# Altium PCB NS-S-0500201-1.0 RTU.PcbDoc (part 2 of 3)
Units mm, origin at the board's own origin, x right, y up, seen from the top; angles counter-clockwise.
Board outline 170 x 90 mm, 6 copper layers (TOP, L2_GND, L3_SIG, L4_VCC, L5_GND, BOT), stack 1.4 mm thick; 260 components, 230 nets, 1133 pads, 705 vias.
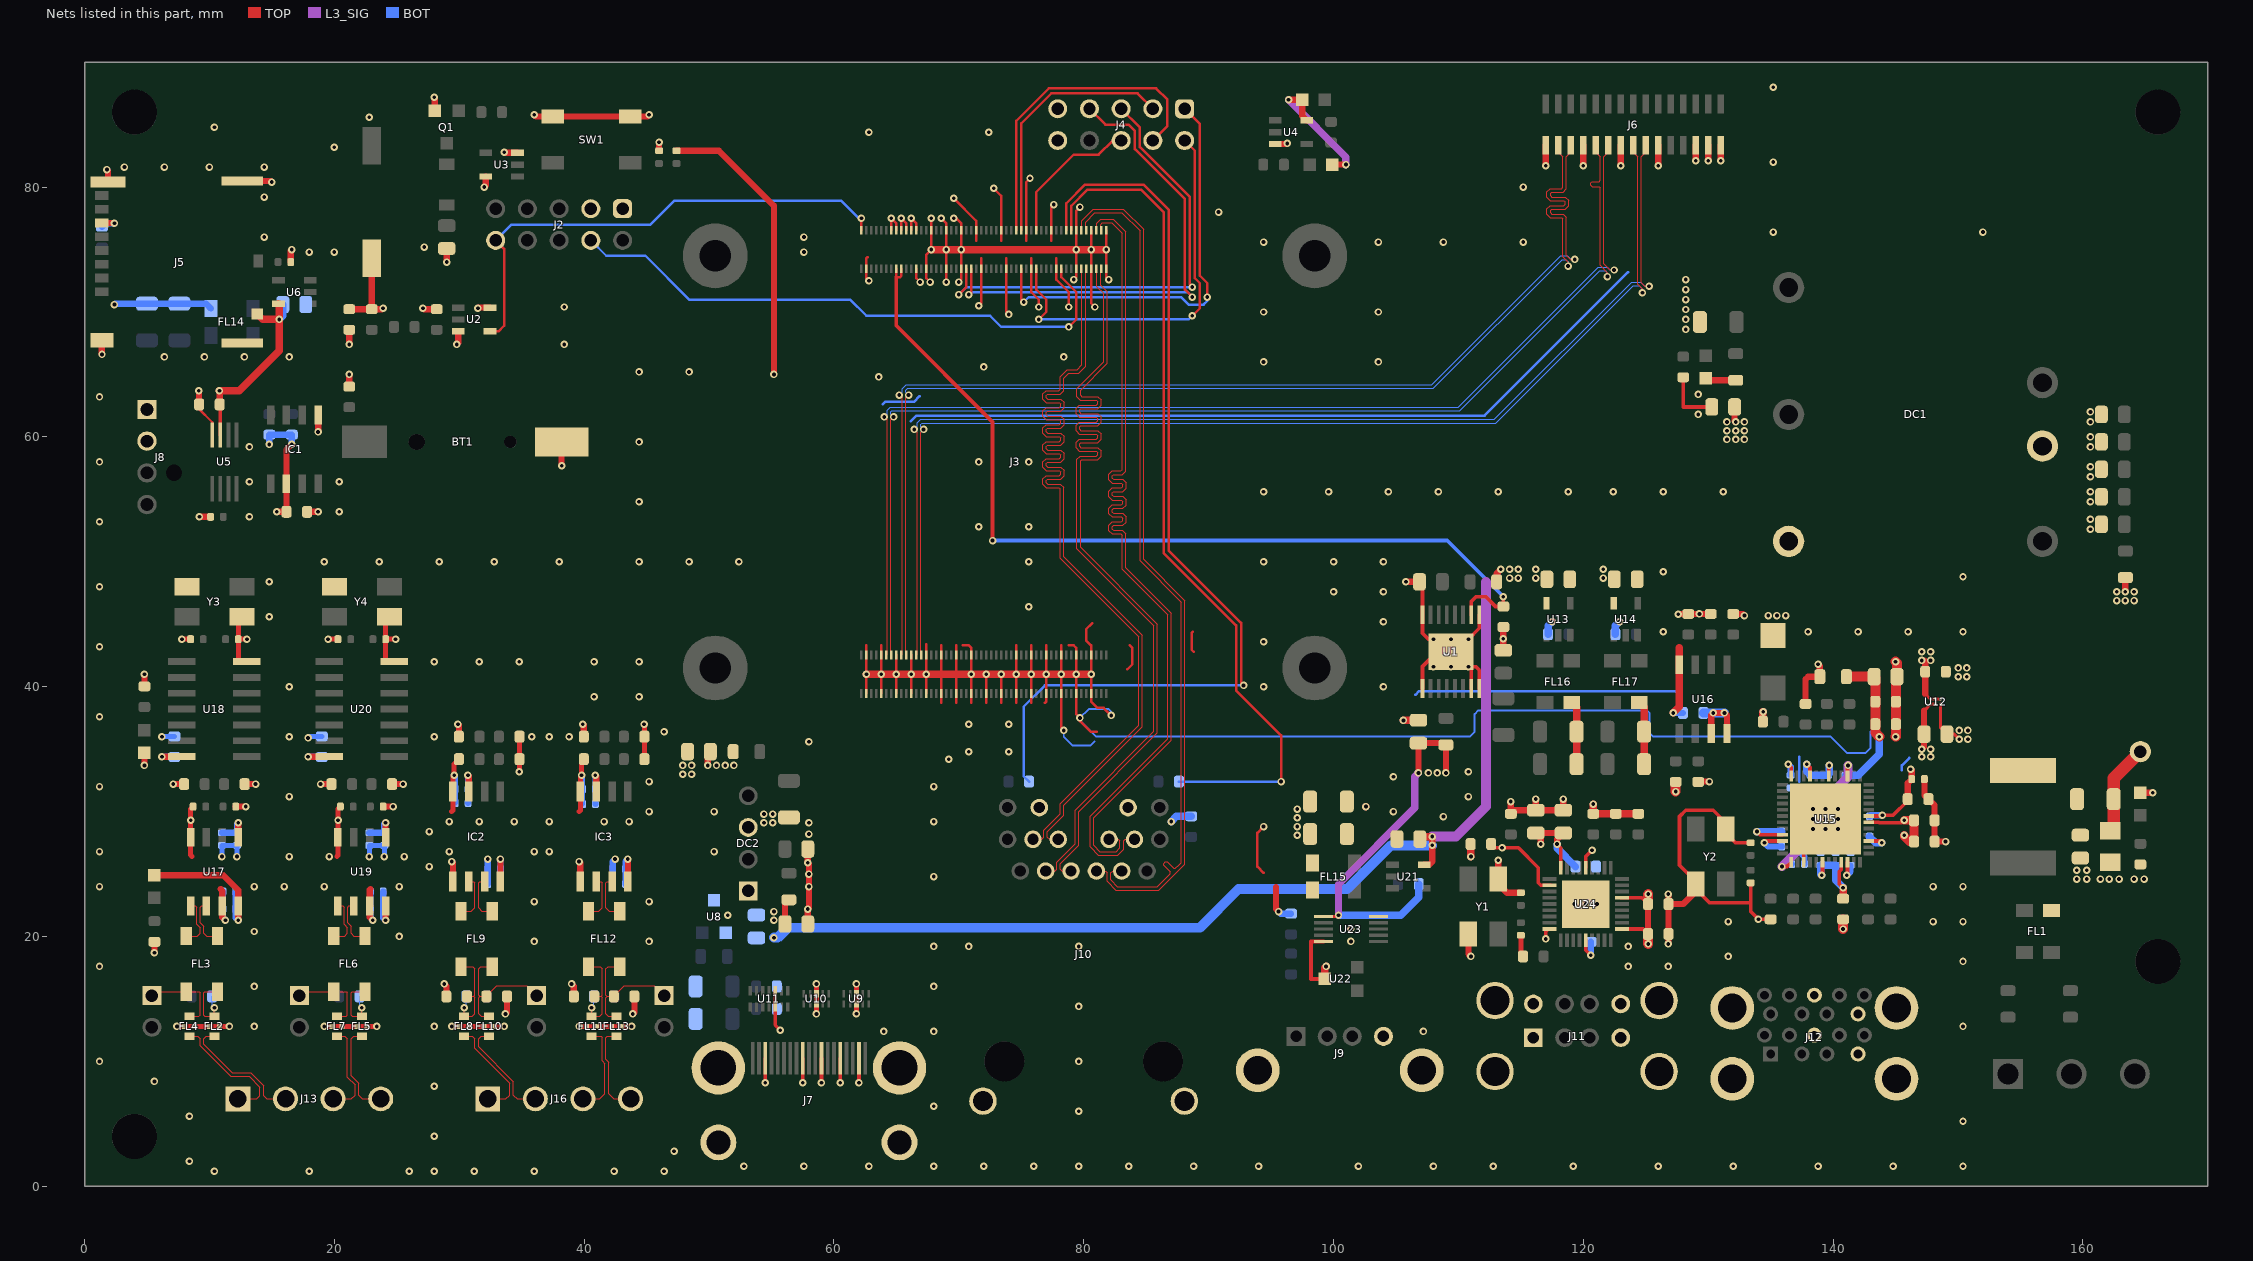
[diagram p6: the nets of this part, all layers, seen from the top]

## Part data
3V3 5V 5V_ISO 24V CPU_RUN PWR_ON: "Standard LEDs - SMD SMD 1608(mm) GREEN", Package=1608, PartNo.="LED GREEN[1608]"
BT1: "Battery Holder (CR1220 Need)", Package="Battery holder 1220 SMD"
C1 C2 C3 C4 C5: "MLCC - SMD/SMT 35V X5R +/-20% 2012(mm)", Package=2012
C8 C11: "Multilayer Ceramic Capacitors MLCC - SMD/SMT 2Kvolts 1000pF 10% X7R", Package=3216
C9 C10 C12 C13 C16 C17 C18 C29 C30 C35 C36 C37 C64 C67 C68 C77: "MLCC - SMD/SMT 50V X5R +/-10% 2012(mm)", Package=2012
C14 C15 C26: library part "C [3216]_10V", "MLCC - SMD/SMT 10V X5R +/-10% 3216(mm)", Package=3216
C19 C45 C46 C47 C48 C49 C53 C54 C55 C56 C57 C58 C61 C62 C65 C66 C85 C86 C88 C89 C90 C91 C93 C94 C95 C96 C98 C99 C100 C101 C102 C103 C104 C105 C106 C107 C108 C109 C112 C113 C114 C115: "MLCC - SMD/SMT 50V X5R +/-10% 1005(mm)", Package=1005
C20 C21 C22 C23 C24 C25 C33 C34 C38 C39 C40 C41 C42 C43 C44 C50 C51 C52 C59 C60 C63 C78 C79 C80 C81 C82 C83 C84 C87 C92 C97 C110 C111 C116 C117: "MLCC - SMD/SMT 50V X5R +/-10% 1608(mm)", Package=1608
C27 C28 C31 C32 C69 C70 C71 C72 C73 C74: "MLCC - SMD/SMT 50V X5R +/-10% 3216(mm)", Package=3216
D1: "Diodes - General Purpose, Power, Switching SURFACE MOUNT FAST SWITCHING DIODE", Manufacturer_Name="Diodes Inc.", Mouser Part Number=621-1N4148W-F, Package=SOD-123
D2: "Schottky Diodes & Rectifiers 1.0 Amp 40 Volt", Package="SMA (DO-214AC)"
DC1: "20W isolated DC-DC converter DIP package, Ultra-wide input and regulated single output", Package="6-DIP Module"
DC2: "Isolated Module DC DC Converter 1 Output 5V 600mA 4.5V - 5.5V Input", Package="4-SIP Module", Supplier Part Number 1=945-2626-ND
FGND: "TEST POINT 1PI", Package="1mm lead", PartNo.=ST-1-1
FL1 FL14 FL15 FL16 FL17: "CMC,filter , 3.2x2.5x2.2mm,500ohm+/-25%,2A,shd", Package=3225
FL2 FL4 FL5 FL7 FL8 FL10 FL11 FL13: library part YFF18SC1H222M, "Eia Case Size: 0603, Voltage: 50, Cap Value: 472, Tol: +/-20%, Thickness: 0.60 ± 0.10", Arrow Part Number=YFF18SC1H222MT0H0N, Capacitance=4.7nF, Case Code (Imperial)=0603, Case Code (Metric)=1608, Current=1A, DC Resistance (DCR)=300mR, Manufacturer=TDK, Max Operating Temperature=125°C, Min Operating Temperature=-55°C, Supplier Part Number 1=445-16139-1-ND, Tolerance=20%, Voltage Rating=50V
FL3 FL6 FL9 FL12: "CMC 11UH 360MA 2LN SMD AEC-Q200", Case Code (Imperial)=1812, Case Code (Metric)=4532, Current=360mA, DC Resistance (DCR)=500mR, Inductance=11uH, Manufacturer=Murata, Manufacturer_Name="Murata Electronics", Max Operating Temperature=125°C, Min Operating Temperature=-40°C, Mouser Part Number=81-DLW43SH110XK2L, Package Quantity=1, Test Frequency=100MHz, Tolerance=50%
FUSE1: "Resettable Fuses - PPTC PTC RESETTABLE 1.85A 33V SMD 2920", Package=2920(7351), Supplier Part Number 1=652-MF-LSMF185/33X-2
H1 H2 H3 H4: "HOLE", Package=Hole
IC1: "DS3232M Series 4.5 V ±5 ppm Surface Mount I2C Real-Time Clock - SOIC-8", Case/Package=SOIC, Manufacturer=Maxim, Manufacturer_Name="Maxim Integrated", Max Operating Temperature=85°C, Max Supply Voltage=4.5V, Min Operating Temperature=-40°C, Min Supply Voltage=2.3V, Mouser Part Number=700-DS3232MZ+, Package=SOIC-8, Package Quantity=100
IC2 IC3: "RS422/RS485 Transceiver, -40 to 85DEG C Rohs Compliant: Yes", Manufacturer=Maxim, Package=SOIC-Wide-8, PartNo.=MAX22026AWA+, Supplier Part Number 1=700-MAX22026AWA+
J1: "Connector"
J2 J4: "Headers & Wire Housings 10P M PIN HEADER DR STRAIGHT TYPE GOLD", Package="2.54mm Dual 26pin Header straight type", Supplier Part Number 1=798-A110PA254DSA71
J3: "Board to Board & Mezzanine Connectors 100P 2R 3MM RECPT SMT VERT 0.4MM PITCH", Package="0.4mm 100p", Supplier Part Number 1=798-DF40HC30100DS451
J5: "Memory Card Connectors MICRO SD PUSH/PUSH NORMAL 1.28MM 8C", Package="Micro SD"
J6: "Raspberry Pi Accessories Replacement CSI/DSI Connector for Raspberry Pi - Repair Part", Package="FPC 1mm 15pin", Supplier Part Number 1=485-4728
J7: library part 2086581051, "HDMI 2.1 Receptacle Connector 19 Position Surface Mount, Right Angle; Through Hole", Package=HDMI, Supplier Part Number 1=538-208658-1051
J8: "KK 254 Vertical Header, with Friction Lock, 4 Circuits, PC Tail Length 3.50mm, Bag", Current Rating=4A, Housing Color=Beige, Max Operating Temperature=75°C, Min Operating Temperature=0°C, Package Quantity=12000, Supplier Part Number=538-47053-1000, Voltage Rating=250V
J9: "USB 2.0 A/F Connector, Right angle", Package="USB2.0 A/F"
J10: "Gigabit Ethernet Connectors 8/8 RA Magnetic Jack Grn/Orange/Grn LED", Package=RJ45, Supplier Part Number 1=538-85793-1003
J11: "USB 2.0 A/F 2 stack Connector, Right angle", Package="USB2.0 A/F"
J12: "USB 3.0 A/F 2 stack Connector, Right angle", Package="USB3.0 A/F"
J13 J16: "Through Hole 4p right angle DIP (MRT8P3.81-04P need)", Package="Through Hole 4p right angle DIP"
J14 J15 J17 J18: "Headers & Wire Housings 2P M PIN HEADER SR STRAIGHT TYPE GOLD", Package="2P Dual Straight DIP Through Hole", Supplier Part Number 1=H123034-ND
L1 L2 L5 L6 L7 L8 L9 L10 L11 L12: "Ferrite Beads Multi-Layer 120Ohm 25% 100MHz 3A 30mOhm DCR 0805 Paper T/R", Case Code (Imperial)=0805, Case Code (Metric)=2012, Current Rating=3A, DC Resistance (DCR)=30mR, Manufacturer=Murata, Max Operating Temperature=125°C, Min Operating Temperature=-55°C, Package="SMD 2012", Package Quantity=1, Supplier Part Number 1=81-BLM21PG121SN1D, Test Frequency=100MHz, Tolerance=25%
LS1: "9 mm, 5 Vdc, 90 dB, SMD Passive, Magnetic Audio Indicator Buzzer"
Q1: "MOSFET (N-Channel)", Manufacturer_Name="ON Semiconductor", Mouser Part Number=512-BSS138
R1 R2 R3 R4 R8 R9 R12 R13 R14 R15 R21 R22 R28 R29 R30 R31 R32 R33 R34 R35 R36 R37 R38 R39 R40 R41 R42 R43 R44 R45 R46 R47 R48 R49 R50 R51 R52 R53 R54 R55 R56 R57 R58 R59 R60: "SMD  Chip Resistor +/-5% 1608(mm)", Package=1608/J
R5: "SMD  Chip Resistor +/-5% 2012(mm)", Package=2012/J
R6 R11: "SMD  Chip Resistor +/-1% 1608(mm)", Package=1608
R7: "SMD  Chip Resistor +/-1% 2012(mm)"
R10 R16 R17: "SMD  Chip Resistor +/-1% 1005(mm)", Package=1005/F
SW1: "SMD type SWITCH", Package="SMD Switch"
U1: "LDO Regulator Pos 3.3V 3A 16-Pin TSSOP EP", Case/Package=TSSOP, Dropout Voltage=340mV, Manufacturer="Analog Devices / Linear Technology", Manufacturer_Name="Analog Devices", Max Operating Temperature=125°C, Min Current Limit=3.1A, Min Operating Temperature=-40°C, Mouser Part Number=584-LT1764EFE-3.3PBF, Output Current=3A, Output Voltage=3.3V, Package=TSSOP-16, Package Quantity=95
U2 U3 U4: "Buffers & Line Drivers Single Schmitt-Trgr", Package=SOT-23-5, PartNo.=SN74LVC1G17DBV, Supplier Part Number 1=595-SN74LVC1G17DBVR
U5: "Board Mount Temperature Sensors Single RPB-Based PWM Fan Speed CNTRL", Package=MSOP-8, Supplier Part Number 1=886-EMC2301-1-ACZLTR
U6: "Power Switch ICs - Power Distribution 70mohm, 1A High-Side Power Switches with flag", Package=TSOT-23-5, Supplier Part Number 1=835-RT9742GGJ5
U8: "Power Switch ICs - Power Distribution 70mohm, 0.5A High-Side Power Switches, Current Limiter", Package=SOT-23-3, Supplier Part Number 1=835-RT9742SNGV
U9 U10: "ESD Suppressors / TVS Diodes Quad 0.5-pF, 3.6-V, 12-kV ESD protection diode for USB &amp; HDMI 10-USON -40 to 125", Package=USON-10, Supplier Part Number 1=595-ESD224DQAR
U11: "ESD Suppressors / TVS Diodes 6-CH lo cap IEC ESD protect diodes", Package=USON-14
U12: "LDO Voltage Regulators 3V~5.5V to 1.05V 1A ultra low-dropout LDO bias", Package=WLCSP-6, Supplier Part Number 1=511-LD57100J105R
U13 U14 U21: "Power Switch ICs - Power Distribution 70mohm, 2A High-Side Power Switches with flag", Package=TSOT-23-5, Supplier Part Number 1=835-RT9742CGJ5
U15: "PD720202 is a USB host controller LSI compatible with the USB 3.0 and xHCI (eXtensible Host Controller Interface) 1.0 specifications. The system bus is compatible with the PCIe Gen2 specification. The controller provides two USB ports with LS (Low-Speed) / FS (Full-Speed) / HS (High-Speed) / SS (SuperSpeed) support.PD720202 comes in a 48-pin QFN package and has the following improvements over previous products.	Reduced power consumption in low-power mode to 4.5mW, a reduction of 90% compared with Renesas", Manufacturer_Name="Renesas Electronics", Mouser Part Number=968-D720202K8701BAAA, Package=QFN-48
U16: "NOR Flash 512 Kbit, 3.0V (2.3V to 3.6V), -40C to 85C, SOIC-N 150mil (Tube), Single, Dual SPI NOR flash", Package=8-SOIC
U17 U19: "CAN Interface IC Isolated CAN FD transceiver in small package 8-SOIC -40 to 125", Package=8-SOIC, Supplier Part Number 1=595-ISO1044BD
U18 U20: "CAN Interface IC Stand-alone Low Power CAN FD Controller s/SPI Interface Grade 0", Package=SOIC-14
U22: "ESD Suppressors / TVS Diodes 2Ch ESD Solution", Package=SOT-3, PartNo.=Package
U23: "USB Switch ICs Low Power, Two-Port USB 2.0 (480Mbps)", Package=MSOP-10, Supplier Part Number 1=512-FSUSB42MUX
U24: "USB Interface IC 2-Port USB 2.0 Hi-Speed Hub Cont", Package=SQFN-36, Supplier Part Number 1=579-USB2512B-I/M2
Y1 Y2: "Crystal 24MHz ±30ppm (Tol) ±50ppm (Stability) 20pF FUND 80Ohm 4-Pin Mini-SMD T/R", Package="5 mm x 3.2 mm", Supplier Part Number 1=520-ECS-240-20-30B
Y3 Y4: "Crystal 40MHz ±30ppm (Tol) ±100ppm (Stability) 20pF FUND 100Ohm 4-Pin Mini-SMD T/R", Package="5 mm x 3.2 mm", Supplier Part Number 1=520-400-20-30B-DU

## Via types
v1: diameter 0.6, hole 0.3, TOP to BOT, tented both sides, 705 vias

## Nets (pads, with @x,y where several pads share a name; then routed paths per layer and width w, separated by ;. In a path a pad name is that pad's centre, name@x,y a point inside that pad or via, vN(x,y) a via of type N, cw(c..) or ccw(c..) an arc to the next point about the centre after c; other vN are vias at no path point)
1V05: C50.1 C51.1 C52.1 C53.1 C54.1 C55.1 C56.1 C57.1 C58.1 C64.1 U12.A1 U12.B1 U15.6 U15.9 U15.21 U15.30 U15.33 U15.39 U15.42 | length 30.6
  TOP w0.25: 147.285,38.085 U12.A1@147.8,38.6 U12.B1@148.2,38.6
  TOP w0.3: v1(133.9,28.4) 134.15,28.15 U15.21@135.95,28.15 ; v1(137.9,33.8) 138.15,33.55 U15.9@138.15,32.85 ; v1(139.1,24.9) 139.15,24.95 U15.30@139.15,25.95 ; U15.6@139.65,32.85 139.65,33.65 v1(139.7,33.7) ; U15.33@140.65,25.95 140.65,25.35 140.5,25.2 140.5,24.2 v1(140.8,23.9) ; U15.39@142.85,27.65 143.75,27.65 v1(143.9,27.5) ; U15.42@142.85,29.15 143.65,29.15 143.7,29.1 145.5,29.1 v1(145.7,29.3)
  TOP w0.5: v1(147.1,35) 147.285,35.185 C64.1@147.285,36.2 147.285,38.085
  TOP w0.6: C50.1@140.8,23.025 v1(140.8,23.9)
  TOP w0.7: v1(145.7,28.1) 145.7,28 146.1,27.6 C52.1@146.475,27.6 C51.1@146.475,29.3 v1(145.7,29.3)
  BOT w0.6: v1(133.9,28.4) C53.1@135.89,28.4 ; v1(137.9,33.8) 137.9,33.21 C58.1@138.2,32.91 C57.1@139.6,32.91 139.7,33.01 v1(139.7,33.7) ; v1(139.1,24.9) 139,25 C54.1@139,25.69 C56.1@140.2,25.69 140.2,24.5 v1(140.8,23.9) ; C55.1@142.91,28 143.41,27.5 v1(143.9,27.5)
  other v1: 147.1,34.4 147.8,34.4 147.8,35
3V3: 3V3.1 C13.1 C20.1 C25.1 C29.2 C36.2 C37.2 C38.1 C39.1 C40.1 C41.1 C42.1 C44.1 C45.1 C46.1 C47.1 C48.1 C49.1 C87.1 C88.1 C89.1 C92.1 C97.1 C102.1 C103.1 C106.1 C107.1 C112.1 C113.1 CPU_RUN.1 D2.1 IC1.2 IC2.3 IC3.3 J3.78 J5.9 J6.14 J6.15 J10.14 J10.15 L6.2 L9.1 PWR_ON.1 R8.2 R9.2 R10.2 R16.2 R28.1 R29.1 R30.1 R32.1 R33.1 R34.1 R35.1 R37.1 R38.1 R40.1 R41.1 R44.1 R49.1 R53.1 U4.5 U5.3 U6.5 U15.12 U15.22 U15.34 U15.43 U16.7 U16.8 U17.1 U18.14 U19.1 U20.14 U23.1 U24.5 U24.10 U24.15 U24.23 U24.27 U24.29 U24.36 | length 182
  TOP w0.2: J3.78@66.6,73.46 66.6,72.7 v1(66.9,72.4)
  TOP w0.25: U23.1@99.2,21.6 100.3,21.6 v1(100.4,21.7)
  TOP w0.3: C25.1@10.825,62.6 10.875,62.55 U5.3@10.875,60.15 ; C38.1@112.625,27.4 112.925,27.1 v1(113.5,27.1) 114.8,27.1 116.4,25.5 116.4,24.3 116.6,24.1 U24.29@117.4,24.1 ; v1(117,19.8) 117,20.4 117.2,20.6 U24.36@117.3,20.6 ; v1(117.9,27.4) 118.2,27.1 U24.27@118.2,25.4 ; U24.5@120.2,19.7 120.2,18.9 v1(120.6,18.5) ; U24.23@120.2,25.5 120.2,26.4 v1(120.7,26.9) ; U24.10@123,20.6 124.775,20.6 C39.1@125.175,20.2 ; U24.15@123,23.1 124.675,23.1 C40.1@125.175,22.6 ; v1(134.5,27.5) 134.5,27.6 134.55,27.65 U15.22@135.95,27.65 ; v1(136.4,33.8) 136.65,33.55 U15.12@136.65,32.85 ; v1(141.1,24.9) 141.15,24.95 U15.34@141.15,25.95 ; U15.43@142.85,29.65 143.9,29.65 v1(143.95,29.7) 144.8,29.7 145.975,30.875 C44.1@145.975,31
  TOP w0.5: v1(4.8,33.7) 3V3.1@4.8,34.7 ; v1(6.2,34.4) U18.14@7.8,34.4 ; v1(7.1,32.2) R37.1@7.975,32.2 ; v1(9.2,53.6) R16.2@10.09,53.6 ; v1(10.8,63.7) 10.825,63.675 C25.1@10.825,62.6 ; v1(12.3,29.1) 12.305,29.095 U17.1@12.305,27.95 ; R38.1@12.825,32.2 v1(13.7,32.2) ; v1(15.4,54) C20.1@16.175,54 16.165,54.01 IC1.2@16.165,56.25 16.165,58.965 v1(16.6,59.4) ; v1(17.9,34.4) U20.14@19.6,34.4 ; v1(18.9,32.2) R40.1@19.775,32.2 ; v1(24.1,29.1) 24.105,29.095 U19.1@24.105,27.95 ; R41.1@24.625,32.2 v1(25.5,32.2) ; v1(29.9,37) 29.975,36.925 R44.1@29.975,36 ; v1(30.7,32.9) 30.765,32.835 IC2.3@30.765,31.6 ; v1(39.9,37) 39.975,36.925 R49.1@39.975,36 ; v1(40.9,32.9) 40.965,32.835 IC3.3@40.965,31.6 ; R10.2@47.4,82.91 50.79,82.91 55.2,78.5 v1(55.2,65) ; v1(96.4,87) PWR_ON.1@97.5,87 97.5,85.7 97.85,85.35 U4.5@97.87,85.35 ; CPU_RUN.1@99.9,81.8 v1(101,81.8) ; v1(106.8,33.1) C13.1@106.8,35.485 108.853,35.485 L6.2@109,35.337 v1(109,33.1) ; v1(116.6,27.4) 116.6,27.885 C36.2@116.2,28.285 C37.2@118.4,28.285 117.9,27.785 v1(117.9,27.4) ; C39.1@125.175,20.2 C40.1@125.175,22.6 ; v1(127.6,45.8) 127.625,45.825 R34.1@128.4,45.825 v1(129.3,45.825) R33.1@130.2,45.825 ; v1(130,82.1) J6.14@130,83.35 ; U16.7@130.235,36.25 130.235,37.735 v1(130.4,37.9) v1(131.3,37.9) 131.505,37.695 U16.8@131.505,36.25 ; v1(131,82.1) J6.15@131,83.35 ; R32.1@132,45.825 132.775,45.825 v1(132.9,45.7) ; R30.1@137.8,38.625 137.8,40.6 138,40.8 L9.1@138.937,40.8 138.937,41.662 v1(138.8,41.8) ; C44.1@145.975,31 145.975,32.285 C47.1@146.29,32.6 146.29,33.31 v1(146.2,33.4)
  TOP w0.6: v1(10.8,63.7) 12.4,63.7 15.6,66.9 v1(15.6,69.4) ; J5.9@13.84,69.83 14.27,69.4 v1(15.6,69.4) ; U6.5@15.53,70.65 15.6,70.58 v1(15.6,69.4)
  TOP w0.8: C39.1@125.175,20.2 125.175,19.425 v1(125.2,19.4) ; C40.1@125.175,22.6 125.175,23.375 v1(125.2,23.4) ; v1(127.4,31.6) R35.1@127.4,32.375
  L3_SIG w0.6: v1(96.4,87) 101,82.4 v1(101,81.8) ; v1(100.4,21.7) 100.4,24.2 106.5,30.3 106.5,32.8 v1(106.8,33.1)
  BOT w0.5: v1(6.2,34.4) 7.175,34.4 C92.1@7.2,34.375 ; C88.1@11,28.31 C89.1@12.2,28.31 12.2,29 v1(12.3,29.1) ; v1(14.8,59.4) R8.2@14.8,60.175 R9.2@16.6,60.175 v1(16.6,59.4) ; v1(17.9,34.4) 18.975,34.4 C97.1@19,34.375 ; C102.1@22.8,28.31 C103.1@24,28.31 24,29 v1(24.1,29.1) ; v1(30.7,32.9) 30.71,32.89 C107.1@30.71,31.8 C106.1@30.71,30.68 ; v1(40.9,32.9) 40.91,32.89 C113.1@40.91,31.8 C112.1@40.91,30.6 ; v1(120.6,18.5) C42.1@120.6,19.575 ; v1(134.5,27.5) 134.8,27.2 C48.1@135.89,27.2 ; v1(136.4,33.8) 136.6,33.6 C45.1@136.6,32.91 ; v1(141.1,24.9) 141.4,25.2 C46.1@141.4,25.69 ; C49.1@142.91,29.6 143.01,29.7 v1(143.95,29.7)
  BOT w0.6: v1(15.6,69.4) 15.885,69.685 C29.2@15.885,70.6 ; v1(100.4,21.7) 105.4,21.7 106.825,23.125 R53.1@106.825,24.2 ; R28.1@117.175,44.2 117.175,44.875 v1(117.5,45.2) ; v1(117.9,27.4) 117.9,27.075 C41.1@119.375,25.6 ; R29.1@122.575,44.2 122.575,44.875 v1(122.9,45.2)
  BOT w0.7: C87.1@129.625,37.9 v1(130.4,37.9) v1(131.3,37.9)
  other v1: 107.6,33.1 108.3,33.1 134.8,45.7 135.5,45.7 136.2,45.7
3V3A: C59.1 C60.1 C61.1 C62.1 C77.2 L9.2 U15.3 U15.25 | length 26.9
  TOP w0.3: v1(135.9,25.6) 136.3,25.6 U15.25@136.65,25.95 ; U15.3@141.15,32.85 141.15,33.65 v1(141.2,33.7)
  TOP w0.8: L9.2@141.062,40.8 C77.2@143.285,40.8 143.375,40.71 C60.1@143.375,38.8 C59.1@143.375,37 143.375,36.325 v1(143.7,36)
  L3_SIG w0.7: v1(135.9,25.6) 137.2,26.9 137.2,30.6 138.4,31.8 140.2,31.8 141.2,32.8 v1(141.2,33.7)
  BOT w0.5: v1(135.9,25.6) 136.1,25.8 C62.1@136.69,25.8
  BOT w0.6: v1(141.2,33.7) 141.2,33.11 C61.1@141,32.91 142.01,32.91 143.7,34.6 v1(143.7,36)
5V: 5V.1 C9.2 C17.2 C22.1 C30.2 C35.2 C63.1 C67.2 C68.2 J3.77 J3.79 J3.81 J3.83 J3.85 J3.87 J4.9 J8.2 L2.2 L5.1 L7.1 LS1.P R7.2 R12.2 R13.2 U2.5 U3.5 U8.1 U12.A2 U12.B2 U12.C2 U13.5 U14.5 U21.5 | length 111.3
  TOP w0.2: J3.87@64.6,76.54 v1(64.6,77.5) 65,77.1 J3.85@65,76.54 ; J3.83@65.4,76.54 v1(65.4,77.5) 65.8,77.1 J3.81@65.8,76.54 ; J3.79@66.2,76.54 v1(66.2,77.5) 66.6,77.1 J3.77@66.6,76.54
  TOP w0.25: 147.375,39.425 147.4,39.4 U12.A2@147.8,39 U12.B2@148.2,39 U12.C2@148.6,39
  TOP w0.5: C22.1@21.2,70.225 R12.2@23,70.225 ; LS1.P@23,74.3 R12.2@23,70.225 ; v1(23.9,70.3) 23.825,70.225 R12.2@23,70.225 ; v1(27.1,70.3) 27.175,70.225 R13.2@28.2,70.225 ; v1(29,74) R7.2@29,75.085 ; v1(31.5,70.3) 31.55,70.35 U2.5@32.47,70.35 ; v1(32,80) 32.13,80.13 U3.5@32.13,80.85 ; C17.2@56.085,21 56.085,22.623 L7.1@56.4,22.938 ; U21.5@107.27,25.75 107.65,25.75 107.9,26 v1(107.9,27.3) v1(107.9,28) ; L5.1@113.062,48.4 113.062,49.063 v1(113.4,49.4) ; 5V.1@129.8,64.7 129.963,64.537 L2.2@132.2,64.537 ; C9.2@132.115,62.4 132.115,61.285 v1(132.2,61.2) ; v1(147.1,42.1) 147.3,42.1 147.375,42.025 C63.1@147.375,41.2 147.375,39.425
  TOP w0.6: C35.2@106.915,27.8 107.115,28 v1(107.9,28)
  L3_SIG w0.8: v1(107.9,28) 109.8,28 112.2,30.4 112.2,48.4
  BOT w0.8: v1(55.2,19.9) 55.5,19.9 56.3,20.7 89.3,20.7 92.4,23.8 101.1,23.8 104.6,27.3 v1(107.9,27.3)
  other v1: 55.2,21.3 55.2,22 147.8,42.1 147.1,42.8 147.8,42.8 114.1,48.7 114.8,48.7 116.2,48.7 121.6,48.7 114.1,49.4 114.8,49.4 116.2,49.4 121.6,49.4 131.5,59.8 132.2,59.8 132.9,59.8 131.5,60.5 132.2,60.5 132.9,60.5 131.5,61.2 132.9,61.2
5V_ISO: 5V_ISO.1 C16.2 C90.1 C91.1 C104.1 C105.1 C108.1 C109.1 C114.1 C115.1 IC2.8 IC3.8 L8.2 R43.2 R48.2 U17.8 U19.8 | length 26.5
  TOP w0.5: 5V_ISO.1@5.6,24.9 11.1,24.9 12.305,23.695 U17.8@12.305,22.45 12.305,21.305 v1(12.3,21.3) ; v1(24.1,21.3) 24.105,21.305 U19.8@24.105,22.45 ; v1(28.8,16.2) 28.975,16.025 R43.2@28.975,15.2 ; v1(33.3,26.2) 33.305,26.195 IC2.8@33.305,24.4 ; v1(39,16.2) 39.175,16.025 R48.2@39.175,15.2 ; v1(43.5,26.2) 43.505,26.195 IC3.8@43.505,24.4 ; v1(49.9,33.7) 49.9,34.585 C16.2@50.115,34.8
  BOT w0.5: C91.1@12.11,23.6 C90.1@12.11,22.2 12.11,21.49 v1(12.3,21.3) ; C104.1@23.91,23.6 C105.1@23.91,22.2 23.91,21.49 v1(24.1,21.3) ; v1(33.3,26.2) 33.31,26.19 C108.1@33.31,25.4 C109.1@33.31,24.2 ; C115.1@43.31,24.2 C114.1@43.31,25.4 43.31,26.01 v1(43.5,26.2)
  other v1: 50.6,33.7 51.3,33.7 52,33.7
5V_USB: C69.2 C70.2 FL15.2 J11.1 J11.5
  other v1: 97.1,28.1 97.1,28.8 97.1,29.5 97.1,30.2
24V: 24V.1 C8.2 C10.1 FUSE1.2 L1.1 | length 2.1
  TOP w0.5: v1(163.4,47.6) L1.1@163.4,48.737 ; 24V.1@164.6,31.5 v1(165.6,31.5)
  other v1: 162.7,46.9 163.4,46.9 164.1,46.9 162.7,47.6 164.1,47.6
485A1_N: FL9.3 FL10.1 J17.1 R46.2 | length 11
  TOP w0.09: FL10.1@32.4,13.6 31.745,13.6 31.55,13.795 31.55,15.105 31.645,15.2 ; FL9.3@32.65,17.575 31.72,17.575 31.545,17.4 31.545,15.3 31.645,15.2 ; J17.1@36.2,15.27 35.42,16.05 33.025,16.05 R46.2@32.175,15.2 31.645,15.2
485A1_P: FL8.1 FL9.2 R43.1 R47.2 | length 8
  TOP w0.09: FL9.2@30.15,17.575 31.08,17.575 31.255,17.4 31.255,15.3 31.155,15.2 ; v1(30.4,14.3) FL8.1@30.4,13.6 31.055,13.6 31.26,13.805 31.26,15.095 31.155,15.2 ; R43.1@30.625,15.2 31.155,15.2
  BOT w0.09: v1(30.4,14.3) 30.575,14.475 R47.2@30.575,15.2
485A2_N: FL9.4 IC2.7 | length 3.8
  TOP w0.09: IC2.7@32.035,24.4 31.645,24.4 31.545,24.3 31.545,22.3 31.82,22.025 FL9.4@32.65,22.025
485A2_P: FL9.1 IC2.6 | length 3.8
  TOP w0.09: FL9.1@30.15,22.025 30.98,22.025 31.255,22.3 31.255,24.3 31.155,24.4 IC2.6@30.765,24.4
485A_N: FL10.3 J16.2 | length 8.5
  TOP w0.09: FL10.3@32.4,12 31.745,12 31.545,11.8 31.545,11.155 34.335,8.365 34.335,7.3 34.635,7 J16.2@36.095,7
485A_P: FL8.3 J16.1 | length 8.5
  TOP w0.09: FL8.3@30.4,12 31.055,12 31.255,11.8 31.255,11.035 34.045,8.245 34.045,7.3 33.745,7 J16.1@32.285,7
485B1_N: FL12.3 FL13.1 J18.1 R51.2 | length 11
  TOP w0.09: FL13.1@42.6,13.6 41.945,13.6 41.75,13.795 41.75,15.105 41.845,15.2 ; FL12.3@42.85,17.575 41.92,17.575 41.745,17.4 41.745,15.3 41.845,15.2 ; J18.1@46.4,15.27 45.62,16.05 43.225,16.05 R51.2@42.375,15.2 41.845,15.2
485B1_P: FL11.1 FL12.2 R48.1 R52.2 | length 8
  TOP w0.09: FL12.2@40.35,17.575 41.28,17.575 41.455,17.4 41.455,15.3 41.355,15.2 ; v1(40.6,14.3) FL11.1@40.6,13.6 41.255,13.6 41.46,13.805 41.46,15.095 41.355,15.2 ; R48.1@40.825,15.2 41.355,15.2
  BOT w0.09: v1(40.6,14.3) 40.775,14.475 R52.2@40.775,15.2
485B2_N: FL12.4 IC3.7 | length 3.8
  TOP w0.09: IC3.7@42.235,24.4 41.845,24.4 41.745,24.3 41.745,22.3 42.02,22.025 FL12.4@42.85,22.025
485B2_P: FL12.1 IC3.6 | length 3.8
  TOP w0.09: FL12.1@40.35,22.025 41.18,22.025 41.455,22.3 41.455,24.3 41.355,24.4 IC3.6@40.965,24.4
485B_N: FL13.3 J16.4 | length 7.4
  TOP w0.09: FL13.3@42.6,12 41.845,12 41.745,11.9 41.745,10.155 41.955,9.945 41.955,7.4 42.355,7 J16.4@43.715,7
485B_P: FL11.3 J16.3 | length 7.4
  TOP w0.09: J16.3@39.905,7 41.265,7 41.665,7.4 41.665,9.825 41.455,10.035 41.455,11.9 41.355,12 FL11.3@40.6,12
CANA1_N: FL3.2 FL4.1 J14.1 | length 6.7
  TOP w0.09: J14.1@5.4,15.27 5.705,15.575 FL3.2@8.15,15.575 9.18,15.575 9.255,15.5 9.255,13.7 9.155,13.6 FL4.1@8.4,13.6
CANA1_P: FL2.1 FL3.3 R39.2 | length 5.5
  TOP w0.09: v1(10.4,14.3) FL2.1@10.4,13.6 9.645,13.6 9.545,13.7 9.545,15.5 9.62,15.575 FL3.3@10.65,15.575
  BOT w0.09: R39.2@10.225,15.2 10.225,14.475 v1(10.4,14.3)
CANA2_N: FL3.1 U17.5 | length 3.9
  TOP w0.09: FL3.1@8.15,20.025 9.03,20.025 9.255,20.25 9.255,20.695 8.985,20.965 8.985,22.35 8.885,22.45 U17.5@8.495,22.45
CANA2_P: FL3.4 U17.6 | length 3.9
  TOP w0.09: U17.6@9.765,22.45 9.375,22.45 9.275,22.35 9.275,21.085 9.545,20.815 9.545,20.25 9.77,20.025 FL3.4@10.65,20.025
CANA_N: FL4.3 J13.1 | length 10.2
  TOP w0.09: FL4.3@8.4,12 9.055,12 9.255,11.8 9.255,11.235 11.69,8.8 13.19,8.8 14.045,7.945 14.045,7.25 13.795,7 J13.1@12.285,7
CANA_P: FL2.3 J13.2 | length 10.2
  TOP w0.09: FL2.3@10.4,12 9.745,12 9.545,11.8 9.545,11.355 11.81,9.09 13.31,9.09 14.335,8.065 14.335,7.25 14.585,7 J13.2@16.095,7
CANB1_N: FL6.2 FL7.1 J15.1 | length 6.7
  TOP w0.09: J15.1@17.2,15.27 17.505,15.575 FL6.2@19.95,15.575 20.98,15.575 21.055,15.5 21.055,13.7 20.955,13.6 FL7.1@20.2,13.6
CANB1_P: FL5.1 FL6.3 R42.2 | length 5.5
  TOP w0.09: v1(22.2,14.3) FL5.1@22.2,13.6 21.445,13.6 21.345,13.7 21.345,15.5 21.42,15.575 FL6.3@22.45,15.575
  BOT w0.09: R42.2@22.025,15.2 22.025,14.475 v1(22.2,14.3)
CANB2_N: FL6.1 U19.5 | length 3.9
  TOP w0.09: FL6.1@19.95,20.025 20.83,20.025 21.055,20.25 21.055,20.695 20.785,20.965 20.785,22.35 20.685,22.45 U19.5@20.295,22.45
CANB2_P: FL6.4 U19.6 | length 3.9
  TOP w0.09: U19.6@21.565,22.45 21.175,22.45 21.075,22.35 21.075,21.085 21.345,20.815 21.345,20.25 21.57,20.025 FL6.4@22.45,20.025
CANB_N: FL7.3 J13.3 | length 7.6
  TOP w0.09: J13.3@19.905,7 21.365,7 21.665,7.3 21.665,8.135 21.055,8.745 21.055,11.8 20.855,12 FL7.3@20.2,12
CANB_P: FL5.3 J13.4 | length 7.6
  TOP w0.09: FL5.3@22.2,12 21.545,12 21.345,11.8 21.345,8.865 21.955,8.255 21.955,7.3 22.255,7 J13.4@23.715,7
CM4_3V3: J3.84 J3.86 R6.2 U1.10 | length 73.6
  TOP w0.2: J3.86@65,73.46 65,72.8 65.3,72.8 65.4,72.9 J3.84@65.4,73.46
  TOP w0.3: 65,72.8 65,68.9 72.7,61.2 v1(72.7,51.7) ; U1.10@111.025,45.75 111.025,46.825 111.4,47.2 112.2,47.2 112.975,46.425 R6.2@113.6,46.425 v1(113.6,47.2)
  BOT w0.3: v1(72.7,51.7) 109.1,51.7 v1(113.6,47.2)
DGND: BT1.2 C9.1 C12.2 C13.2 C17.1 C18.1 C19.2 C20.2 C21.2 C22.2 C24.2 C25.2 C26.2 C27.1 C28.1 C29.1 C30.1 C31.1 C32.1 C33.2 C34.2 C35.1 C36.1 C37.1 C38.2 C39.2 C40.2 C41.2 C42.2 C43.2 C44.2 C45.2 C46.2 C47.2 C48.2 C49.2 C50.2 C51.2 C52.2 C53.2 C54.2 C55.2 C56.2 C57.2 C58.2 C59.2 C60.2 C61.2 C62.2 C63.2 C64.2 C65.2 C66.2 C67.1 C68.1 C69.1 C70.1 C71.1 C72.1 C73.1 C74.1 C77.1 C82.2 C85.2 C86.2 C87.2 C88.2 C89.2 C92.2 C93.2 C94.2 C95.2 C96.2 C97.2 C98.2 C99.2 C100.2 C101.2 C102.2 C103.2 C106.2 C107.2 C110.2 C111.2 C112.2 C113.2 C116.2 C117.2 DC1.6 DC2.1 FL14.1 FL15.3 FL16.3 FL17.3 IC1.5 IC2.4 IC3.4 J2.1 J2.3 J3.1 J3.2 J3.7 J3.8 J3.13 J3.14 J3.22 J3.23 J3.32 J3.33 J3.42 J3.43 J3.52 J3.53 J3.59 J3.60 J3.65 J3.66 J3.71 J3.74 J3.98 J3.107 J3.108 J3.113 J3.114 J3.119 J3.120 J3.125 J3.126 J3.131 J3.132 J3.137 J3.138 J3.144 J3.150 J3.155 J3.156 J3.161 J3.162 J3.167 J3.168 J3.173 J3.174 J3.179 J3.180 J3.185 J3.186 J3.191 J3.192 J3.197 J3.198 J4.10 J5.6 J5.P1 J5.P2 J5.P3 J5.P4 J6.1 J6.4 J6.7 J6.10 J6.13 J7.2 J7.5 J7.8 J7.11 J7.17 J7.20 J7.21 J7.22 J7.23 J8.1 J9.4 J9.5 J9.6 J10.17 J10.18 J11.4 J11.8 J11.9 J11.10 J11.11 J11.12 J12.4 J12.7 J12.13 J12.16 J12.19 J12.20 J12.21 J12.22 Q1.2 R2.1 R4.1 R5.1 R6.1 R17.1 R31.1 R36.1 R45.2 R50.2 R55.1 R56.1 R57.1 R58.1 R59.1 R60.1 SW1.1 SW1.2 U1.1 U1.7 U1.8 U1.9 U1.16 U1.17 U2.3 U3.3 U4.3 U5.4 U8.3 U9.3 U9.8 U10.3 U10.8 U11.5 U11.10 U12.C1 U15.27 U15.49 U16.4 U17.4 U18.7 U19.4 U20.7 U22.3 U23.5 U23.10 U24.37 Y1.2 Y1.4 Y2.2 Y2.4 Y3.2 Y3.4 Y4.2 Y4.4 | length 605
  TOP w0.2: C25.2@9.175,62.6 9.175,62.225 10.225,61.175 U5.4@10.225,60.15 ; J3.198@62.6,39.46 v1(62.6,41) J3.197@62.6,42.54 62.6,43.3 ; 62.7,74.4 62.6,74.3 J3.98@62.6,73.46 62.6,72.7 v1(62.8,72.5) ; J3.192@63.8,39.46 v1(63.8,41) J3.191@63.8,42.54 63.8,43.3 ; J3.186@65,39.46 v1(65,41) J3.185@65,42.54 ; J3.180@66.2,39.46 v1(66.2,41) J3.179@66.2,42.54 ; J3.174@67.4,39.46 v1(67.4,41) J3.173@67.4,42.54 67.4,43.4 ; v1(67.7,72.4) 67.4,72.7 J3.74@67.4,73.46 67.4,74.6 v1(67.8,75) J3.71@67.8,76.54 v1(67.8,77.5) ; 68.6,38.7 J3.168@68.6,39.46 68.6,41 J3.167@68.6,42.54 68.6,43.3 ; v1(68.6,77.5) 69,77.1 J3.65@69,76.54 v1(69,75) J3.66@69,73.46 v1(69,72.4) ; v1(69.6,77.5) 69.8,77.5 70.2,77.1 J3.59@70.2,76.54 v1(70.2,75) J3.60@70.2,73.46 70.2,72.6 v1(70,72.4) ; v1(69.6,79.1) 71.4,77.3 J3.53@71.4,76.54 71.4,75.7 ; 69.8,38.7 J3.162@69.8,39.46 69.8,41 J3.161@69.8,42.54 69.8,43.3 ; 70.3,43.3 70.8,43.3 71,43.1 J3.155@71,42.54 v1(71,41) J3.156@71,39.46 71,38.7 ; v1(71.6,70.5) 71.8,70.7 J3.52@71.8,73.46 71.8,74.3 ; 72.2,38.7 J3.150@72.2,39.46 v1(72.2,41) ; v1(72.8,79.9) 73.4,79.3 J3.43@73.4,76.54 73.4,75.7 ; 73.4,38.7 J3.144@73.4,39.46 v1(73.4,41) ; 73.8,74.3 J3.42@73.8,73.46 73.8,70 v1(74,69.8) ; 74.6,38.7 J3.138@74.6,39.46 v1(74.6,41) J3.137@74.6,42.54 74.6,43.3 ; 75.4,75.7 J3.33@75.4,76.54 75.4,80.4 v1(75.7,80.7) ; 75.8,38.7 J3.132@75.8,39.46 v1(75.8,41) J3.131@75.8,42.54 75.8,43.3 ; 75.8,74.3 J3.32@75.8,73.46 75.8,71.6 76.4,71 v1(76.4,70.4) ; 76.9,38.7 77,38.8 J3.126@77,39.46 v1(77,41) J3.125@77,42.54 77,43.3 ; 77.4,75.7 J3.23@77.4,76.54 77.4,78.4 v1(77.6,78.6) ; 77.8,74.3 J3.22@77.8,73.46 77.8,72.6 78.8,71.6 v1(78.8,70.4) ; 78.2,43.3 J3.119@78.2,42.54 v1(78.2,41) J3.120@78.2,39.46 78.2,36.7 v1(78.4,36.5) ; 78.8,43.3 79.2,43.3 79.4,43.1 J3.113@79.4,42.54 v1(79.4,41) J3.114@79.4,39.46 79.4,37.8 v1(79.7,37.5) 79.7,37.25 80.55,36.4 81.05,36.4 ; v1(79.2,72.6) 79.4,72.8 J3.14@79.4,73.46 v1(79.4,75) J3.13@79.4,76.54 79.4,78.1 v1(79.7,78.4) ; J3.7@80.6,76.54 v1(80.6,75) J3.8@80.6,73.46 80.6,70.7 v1(80.9,70.4) ; 80.675,45.075 80.2,44.6 80.2,43.7 80.6,43.3 J3.107@80.6,42.54 v1(80.6,41) J3.108@80.6,39.46 80.6,38.8 81.1,38.3 81.6,38.3 v1(82.2,37.7) ; J3.1@81.8,76.54 v1(81.8,75) J3.2@81.8,73.46 81.8,72.8 v1(82,72.6) ; 83.5,41.4 83.9,41.8 83.9,43.1 83.7,43.3 ; 88.75,44.4 88.65,44.3 88.65,42.95 88.8,42.8 ; 94.4,25.1 93.9,25.6 93.9,28.3 v1(94.4,28.8)
  TOP w0.25: U11.10@55.3,15.65 U11.5@55.3,14.35 55.3,12.9 v1(55.7,12.5) ; U12.C1@148.6,38.6 148.6,36.715 C64.2@149.115,36.2 149.7,36.2 v1(150.1,35.8)
  TOP w0.3: v1(54.5,8.3) J7.17@54.5,10.235 ; v1(57.5,8.3) J7.11@57.5,10.235 ; v1(59,8.3) J7.8@59,10.235 ; v1(60.5,8.3) J7.5@60.5,10.235 ; v1(62,8.3) J7.2@62,10.235 ; U23.5@99.2,19.6 98.2,19.6 98.2,16.6 U22.3@99.3,16.6 ; C12.2@106.885,48.4 107.125,48.16 U1.16@107.125,45.75 107.125,44.275 107.6,43.8 v1(108,43.8) 108.4,43.8 U1.17@109.4,42.8 108.3,42.8 107.125,41.625 U1.1@107.125,39.85 ; v1(110.8,43.8) 111.675,44.675 U1.9@111.675,45.75 ; U1.7@111.025,39.85 111.025,41.375 v1(110.8,41.6) 111.4,41.6 111.675,41.325 U1.8@111.675,39.85 ; R2.1@128,64.775 128,62.4 C9.1@130.285,62.4 ; C85.2@133.4,24.29 133.4,22.7 ; C86.2@133.4,27.51 132.19,27.51 131.4,28.3 Y2.2@131.4,28.6 131.4,29.1 130.4,30.1 128.2,30.1 127.7,29.6 127.7,25.7 129,24.4 Y2.4@129,24.2 129,23.8 130.1,22.7 133.4,22.7 ; R31.1@135,21.375 v1(134.025,21.375) 133.4,22 133.4,22.7 ; U15.27@137.65,25.95 137.65,28.65 v1(138.4,29.4)
  TOP w0.4: v1(7.8,43.8) C96.2@8.49,43.8 ; 8.6,26.4 8.495,26.505 U17.4@8.495,27.95 8.495,29.295 v1(8.5,29.3) 8.5,30.21 C94.2@8.69,30.4 ; Y3.4@12.6,45.6 12.31,45.31 C95.2@12.31,43.8 ; U18.7@13,42.02 12.38,42.02 12.31,42.09 C95.2@12.31,43.8 ; v1(13,43.8) C95.2@12.31,43.8 ; v1(19.5,43.8) C101.2@20.29,43.8 ; 20.2,26.4 20.295,26.495 U19.4@20.295,27.95 20.295,29.295 v1(20.3,29.3) 20.3,30.21 C99.2@20.49,30.4 ; Y4.4@24.4,45.6 24.11,45.31 C100.2@24.11,43.8 ; U20.7@24.8,42.02 24.18,42.02 24.11,42.09 C100.2@24.11,43.8 ; v1(24.9,43.8) C100.2@24.11,43.8 ; 29.4,30 29.495,30.095 IC2.4@29.495,31.6 29.495,32.795 v1(29.6,32.9) 29.6,33.825 C111.2@29.975,34.2 ; v1(34.8,33.2) 34.825,33.225 C110.2@34.825,34.2 R45.2@34.825,36 ; 39.6,30 39.695,30.095 IC3.4@39.695,31.6 39.695,32.795 v1(39.8,32.9) 39.8,34.025 C117.2@39.975,34.2 ; v1(44.8,37) 44.825,36.975 C116.2@44.825,34.2 R50.2@44.825,36 ; v1(58.6,13.8) U10.3@58.6,14.583 U10.8@58.6,15.417 v1(58.6,16.2) ; v1(61.8,13.817) U9.3@61.8,14.583 U9.8@61.8,15.417 v1(61.8,16.2) ; C65.2@115,20.09 115,18.575 R60.1@115.175,18.4
  TOP w0.5: J5.6@1.375,77.12 2.38,77.12 v1(2.4,77.1) ; J5.P1@1.39,67.74 1.39,66.61 v1(1.4,66.6) ; v1(1.8,81.4) 1.875,81.325 J5.P2@1.875,80.4 ; R4.1@4.8,40.025 v1(4.8,41) ; v1(9.15,63.7) 9.175,63.675 C25.2@9.175,62.6 ; C93.2@12.11,30.4 v1(12.9,30.4) ; J5.P4@12.64,80.48 14.92,80.48 v1(15,80.4) ; R17.1@16.51,74 16.51,74.91 v1(16.6,75) ; C20.2@17.825,54 v1(18.7,54) ; v1(18.7,60.4) 18.705,60.405 IC1.5@18.705,61.75 ; C21.2@21.2,64.025 v1(21.2,65) ; v1(21.2,67.4) C22.2@21.2,68.575 ; C98.2@23.91,30.4 v1(24.7,30.4) ; v1(28,87.2) 28.05,87.15 Q1.2@28.05,86.1 ; v1(29.8,67.4) 29.93,67.53 U2.3@29.93,68.45 ; v1(33.6,82.8) 33.65,82.75 U3.3@34.67,82.75 ; v1(36,85.8) 36.15,85.65 SW1.1@37.5,85.65 SW1.2@43.7,85.65 45.05,85.65 v1(45.2,85.8) ; v1(38.2,57.7) BT1.2@38.2,59.6 ; C19.2@46,82.91 v1(46,83.6) ; C17.1@57.915,21 57.915,22.185 v1(57.9,22.2) 58,22.3 v1(58,24) v1(58,25) 58,25.8 v1(57.9,25.9) 57.9,26.815 58,26.915 C18.1@57.915,27 ; U4.3@95.33,83.45 96.25,83.45 v1(96.3,83.5) ; 95.4,23.935 95.4,22.2 v1(95.6,22) ; v1(105.8,48.4) C12.2@106.885,48.4 ; Y1.4@110.8,20.2 110.8,18.6 v1(111,18.4) ; v1(113.2,26.1) Y1.2@113.2,24.6 113.2,24.2 113.89,23.51 C66.2@115,23.51 ; R5.1@113.6,42.915 v1(113.6,43.845) R6.1@113.6,44.775 ; v1(114.2,30.8) R58.1@114.2,29.825 114.49,30.115 C36.1@116.2,30.115 ; v1(116.2,31) C36.1@116.2,30.115 ; v1(117,81.7) J6.1@117,83.35 ; v1(118.4,31) C37.1@118.4,30.115 C36.1@116.2,30.115 ; v1(120,81.7) J6.4@120,83.35 ; v1(123,81.7) J6.7@123,83.35 ; v1(126,81.7) J6.10@126,83.35 ; v1(126.8,19.4) 126.825,19.425 C39.2@126.825,20.2 C40.2@126.825,22.6 ; v1(126.8,23.4) 126.825,23.375 C40.2@126.825,22.6 ; Y2.4@129,24.2 129,23.6 128,22.6 C40.2@126.825,22.6 ; v1(129,82.1) J6.13@129,83.35 ; R36.1@129.2,32.375 129.225,32.4 v1(130.1,32.4) ; C47.2@147.31,32.6 147.31,31.315 C44.2@147.625,31 148.125,30.5 C51.2@148.125,29.3 C52.2@148.125,27.6 v1(149,27.6)
  TOP w0.6: v1(62.6,41) v1(63.8,41) v1(65,41) v1(66.2,41) v1(67.4,41) 68.6,41 69.8,41 v1(71,41) v1(72.2,41) v1(73.4,41) v1(74.6,41) v1(75.8,41) v1(77,41) v1(78.2,41) v1(79.4,41) v1(80.6,41) ; v1(67.8,75) v1(69,75) v1(70.2,75) v1(79.4,75) v1(80.6,75) v1(81.8,75) ; U22.3@99.3,16.6 99.3,17.5 v1(99.4,17.6) ; v1(105.6,37.3) 106.785,37.3 C13.2@106.8,37.315 ; C38.2@110.975,27.4 110.975,26.425 v1(111,26.4) ; FL16.3@119.075,38.725 119.465,38.335 C71.1@119.465,36.4 C72.1@119.465,33.8 ; v1(120.8,30.6) R59.1@120.8,29.825 R56.1@122.6,29.825 R57.1@124.475,29.825 ; FL17.3@124.475,38.725 124.865,38.335 C73.1@124.865,36.4 C74.1@124.865,33.8 ; v1(127.2,37.9) 127.695,38.395 U16.4@127.695,41.75 127.695,43.095 127.7,43.1 ; C82.2@134.375,37.2 134.375,37.975 v1(134.4,38)
  TOP w0.8: v1(140.8,20.6) C50.2@140.8,21.375 ; v1(145,36) 145.025,36.025 C59.2@145.025,37 C60.2@145.025,38.8 145.025,40.71 C77.1@145.115,40.8 145.115,41.885 v1(145,42)
  BOT w0.15: v1(78.4,36.5) 78.4,36 79.1,35.3 80.55,35.3 80.85,35.6 ; v1(82.2,37.7) 82.2,38 82,38.2 80.4,38.2 v1(79.7,37.5) 79.7,37.3 81,36 110.9,36 111.3,36.4 111.3,37.8 111.6,38.1 125.1,38.1 125.3,37.9 125.3,36.3 125.6,36 139.8,36 141.1,34.7 142.6,34.7 143,35.1 143,36.4
  BOT w0.2: 63.9,62.6 64.1,62.8 66.4,62.8 66.864,63.264 ; 66.171,61.271 66.6,61.7 112.1,61.7 123.59,73.19 ; 106.55,39.35 106.85,39.65 127.35,39.65 127.6,39.4 ; 137.3,32.4 137.3,34.4 ; C58.2@138.2,31.89 C57.2@139.6,31.89 C61.2@141,31.89 ; 145.5,33.3 145.5,33.7 146.102,34.302
  BOT w0.4: v1(6.2,36) 6.225,36.025 C92.2@7.2,36.025 ; v1(11,26.4) C88.2@11,27.29 C89.2@12.2,27.29 v1(12.2,26.4) ; v1(17.9,35.9) 18.025,36.025 C97.2@19,36.025 ; v1(22.8,26.4) C102.2@22.8,27.29 C103.2@24,27.29 v1(24,26.4) ; v1(29.6,32.9) 29.69,32.81 C107.2@29.69,31.8 C106.2@29.69,30.68 ; v1(39.8,32.9) 39.89,32.81 C113.2@39.89,31.8 C112.2@39.89,30.6
  BOT w0.5: C24.2@1.4,76.825 1.675,77.1 v1(2.4,77.1) ; v1(2.4,70.6) 2.465,70.665 C28.1@5,70.665 C27.1@7.6,70.665 9.735,70.665 FL14.1@10.125,70.275 ; v1(95.6,22) 95.775,21.825 R55.1@96.6,21.825 ; v1(127.2,37.9) C87.2@127.975,37.9 ; C53.2@136.91,28.4 C48.2@136.91,27.2 137.71,26.4 C62.2@137.71,25.8
  BOT w0.6: v1(87,29.2) 87.425,29.625 C43.2@88.6,29.625
  other v1: 52.8,1.6 57.6,1.6 62.8,1.6 68,1.6 72,1.6 76,1.6 79.6,1.6 83.6,1.6 88.8,1.6 94,1.6 102,1.6 108,1.6 112.8,1.6 119.2,1.6 126,1.6 132,1.6 138.8,1.6 144.8,1.6 150.4,1.6 150.4,5.2 79.6,6 68,6.4 79.6,10 64,12.4 68,12.4 107.2,12.4 150.4,12.8 79.6,14.4 68,16 123.6,17.6 126.8,17.6 150.4,18 131.6,18.4 68,19.2 70.8,19.2 79.6,19.2 123.6,19.2 101.4,19.6 101.4,20.6 131.6,21.2 148,21.2 150.4,21.2 51.5,21.7 119.3,22.6 120.2,22.6 121.1,22.6 148,24 150.4,24 68,24.8 16.4,26.4 19.6,26.4 25.6,26.4 1.2,26.8 58,28.2 27.6,28.4 138.4,28.6 139.4,28.6 140.4,28.6 58,29.1 29.2,29.2 31.6,29.2 34.4,29.2 37.2,29.2 41.6,29.2 43.6,29.2 68,29.2 139.4,29.4 140.4,29.4 108.8,29.6 104.8,30 138.4,30.2 139.4,30.2 140.4,30.2 102.6,30.4 16.4,31.2 110.8,31.2 1.2,32 68,32 104.8,32.8 110.8,33.2 69.2,34.2 70.8,34.8 74,34.8 58,35.6 150.8,35.8 16.4,36 28,36 35.8,36 37.2,36 38.8,36 46.4,36.4 150.1,36.5 150.8,36.5 70.8,37 74,37 1.2,37.6 40.8,39.2 44.4,39.2 16.4,40 94.4,40 104,40 150.01,40.8 150.71,40.8 150.01,41.5 150.71,41.5 108,41.6 109.4,41.6 28,42 31.6,42 34.8,42 40.8,42 44.4,42 1.2,43.2 94.4,43.6 109.4,43.8 126.4,44.4 138,44.4 142,44.4 146,44.4 150.4,44.4 104,45.2 14.8,45.6 75.6,46.4 100,47.6 104,47.6 1.2,48 14.8,48.4 150.4,48.8 126.4,49.2 19.2,50 23.6,50 28.4,50 32.8,50 38,50 44.4,50 48.4,50 52.4,50 75.6,50 94.4,50 100,50 104,50 71.6,52.8 75.6,52.8 1.2,53.2 13.2,53.6 20.4,54 44.4,54.8 94.4,55.6 99.6,55.6 104.4,55.6 108.4,55.6 113.2,55.6 118.8,55.6 122.4,55.6 126.4,55.6 131.2,55.6 13.2,56.4 20.4,56.4 1.2,58 71.6,58 75.6,58 13.2,59.2 44.4,59.6 129.2,61.8 1.2,63.2 129.2,63.4 63.6,64.8 44.4,65.2 48.4,65.2 72,65.6 94.4,66 103.6,66 6.4,66.4 9.6,66.4 12.8,66.4 16.4,66.4 78.4,66.4 38.4,67.4 128.2,68.6 128.2,69.4 94.4,70 103.6,70 128.2,70.2 38.4,70.4 128.2,71 128.2,71.8 128.2,72.6 18,74.8 20,74.8 57.6,74.8 27.2,75.2 94.4,75.6 103.6,75.6 108.8,75.6 115.2,75.6 14.4,76 57.6,76 135.2,76.4 152,76.4 90.8,78 14.4,79.2 115.2,80 3.2,81.6 6.4,81.6 10,81.6 14.4,81.6 135.2,82 20,83.2 62.8,84.4 72.4,84.4 10.4,84.8 22.8,85.6 135.2,88
DSI1_C_N: J3.187 J6.5 | length 94.3
  TOP w0.09: J3.187@64.6,42.54 64.545,42.595 64.545,61.37 v1(64.775,61.6) ; J6.5@121,83.35 121,82.8 121.355,82.445 121.355,80.696 121.355,80.534 121.258,80.436 120.698,80.436 120.601,80.339 120.601,80.144 120.698,80.046 121.258,80.046 121.355,79.949 121.355,79.904 121.355,73.735 121.932,73.158 v1(121.932,72.832)
  BOT w0.09: v1(64.775,61.6) 64.545,61.83 64.545,61.995 64.65,62.1 110.1,62.1 121.31,73.31 121.78,73.31 121.932,73.158 v1(121.932,72.832)
DSI1_C_P: J3.189 J6.6 | length 93.5
  TOP w0.09: v1(64.025,61.6) 64.255,61.37 64.255,42.595 J3.189@64.2,42.54 ; J6.6@122,83.35 122,82.8 121.645,82.445 121.645,73.855 122.137,73.363 v1(122.463,73.363)
  BOT w0.09: v1(64.025,61.6) 64.255,61.83 64.255,62.115 64.53,62.39 109.98,62.39 121.19,73.6 121.9,73.6 122.137,73.363 v1(122.463,73.363)
DSI1_D0_N: J3.175 J6.8 | length 93.6
  TOP w0.09: J3.175@67,42.54 66.945,42.595 66.945,60.37 v1(67.175,60.6) ; J6.8@124,83.35 124,82.8 124.355,82.445 124.355,72.235 124.732,71.858 v1(124.732,71.532)
  BOT w0.09: v1(67.175,60.6) 66.945,60.83 66.945,60.995 67.06,61.11 113.01,61.11 124.01,72.11 124.48,72.11 124.732,71.858 v1(124.732,71.532)
DSI1_D0_P: J3.177 J6.9 | length 94.1
  TOP w0.09: v1(66.425,60.6) 66.655,60.37 66.655,42.595 J3.177@66.6,42.54 ; J6.9@125,83.35 125,82.8 124.645,82.445 124.645,72.355 124.937,72.063 v1(125.263,72.063)
  BOT w0.09: v1(66.425,60.6) 66.655,60.83 66.655,61.115 66.94,61.4 112.89,61.4 123.89,72.4 124.6,72.4 124.937,72.063 v1(125.263,72.063)
DSI1_D1_N: J3.181 J6.2 | length 93.8
  TOP w0.09: J3.181@65.8,42.54 65.745,42.595 65.745,63.12 v1(65.975,63.35) ; J6.2@118,83.35 118,82.8 118.355,82.445 118.355,80.793 118.355,79.983 118.258,79.885 117.352,79.885 117.085,79.618 117.085,79.183 117.352,78.915 118.446,78.915 118.543,78.818 118.543,78.623 118.446,78.525 117.352,78.525 117.085,78.258 117.085,77.823 117.352,77.555 118.258,77.555 118.355,77.458 118.355,77.085 118.355,74.435 118.795,73.995 118.795,73.695 v1(118.782,73.682)
  BOT w0.09: v1(65.975,63.35) 65.745,63.58 65.745,63.745 65.9,63.9 108,63.9 118.3,74.2 118.59,74.2 118.782,74.008 v1(118.782,73.682)
DSI1_D1_P: J3.183 J6.3 | length 94.3
  TOP w0.09: v1(65.225,63.35) 65.455,63.12 65.455,42.595 J3.183@65.4,42.54 ; J6.3@119,83.35 119,82.8 118.645,82.445 118.645,80.793 118.645,79.863 118.378,79.595 117.472,79.595 117.375,79.498 117.375,79.303 117.472,79.205 118.566,79.205 118.833,78.938 118.833,78.503 118.566,78.235 117.472,78.235 117.375,78.138 117.375,77.943 117.472,77.845 118.378,77.845 118.645,77.578 118.645,77.085 118.645,74.555 119,74.2 119.3,74.2 v1(119.313,74.213)
  BOT w0.09: v1(65.225,63.35) 65.455,63.58 65.455,63.865 65.78,64.19 107.88,64.19 118.18,74.49 118.71,74.49 118.987,74.213 v1(119.313,74.213)
EEPROM_nWP: J2.4 J3.20 | length 46.5
  TOP w0.2: J3.20@78.2,73.46 78.2,72.8 79.4,71.6 79.4,69.4 v1(78.8,68.8)
  BOT w0.2: J2.4@40.54,75.73 41.77,74.5 44.9,74.5 48.4,71 61.3,71 62.6,69.7 72.5,69.7 73.4,68.8 v1(78.8,68.8)
Ethernet_nLED2: J3.17 R22.2 | length 76.9
  TOP w0.2: J3.17@78.6,76.54 78.6,78.7 80.1,80.2 84.8,80.2 86.8,78.2 86.8,50.9 92.6,45.1 92.6,40.3 v1(92.8,40.1)
  BOT w0.2: R22.2@75.625,32.4 75.2,32.825 75.2,38.4 76.9,40.1 v1(92.8,40.1)
Ethernet_nLED3: J3.15 R21.2 | length 68.3
  TOP w0.2: J3.15@79,76.54 79,78.5 80.3,79.8 84.6,79.8 86.4,78 86.4,50.7 92.2,44.9 92.2,39.7 95.8,36.1 v1(95.8,32.4)
  BOT w0.2: R21.2@87.625,32.4 v1(95.8,32.4)
Ethernet_Pair0_N: J3.10 J10.10 | length 67.9
  TOP w0.09: J10.10@77.965,27.78 77.265,27.78 77.095,27.95 77.095,28.395 78.4,29.7 78.4,30.5 84.7,36.8 84.7,44.1 78.4,50.4 78.4,55.647 78.4,55.957 78.133,56.225 77.114,56.225 77.017,56.322 77.017,56.517 77.114,56.615 78.182,56.615 78.449,56.882 78.449,57.317 78.182,57.585 77.114,57.585 77.017,57.682 77.017,57.877 77.114,57.975 78.182,57.975 78.449,58.242 78.449,58.677 78.182,58.945 77.114,58.945 77.017,59.042 77.017,59.237 77.114,59.335 78.182,59.335 78.449,59.602 78.449,60.037 78.182,60.305 77.114,60.305 77.017,60.402 77.017,60.597 77.114,60.695 78.182,60.695 78.449,60.962 78.449,61.397 78.182,61.665 77.114,61.665 77.017,61.762 77.017,61.957 77.114,62.055 78.182,62.055 78.449,62.322 78.449,62.757 78.182,63.025 77.114,63.025 77.017,63.122 77.017,63.317 77.114,63.415 78.133,63.415 78.4,63.682 78.4,64.612 78.4,64.69 78.81,65.1 79.6,65.1 80.145,65.645 80.145,73.405 J3.10@80.2,73.46
Ethernet_Pair0_P: J3.12 J10.11 | length 67.9
  TOP w0.09: J10.11@75.935,27.78 76.635,27.78 76.805,27.95 76.805,28.515 78.11,29.82 78.11,30.62 84.41,36.92 84.41,43.98 78.11,50.28 78.11,55.647 78.11,55.837 78.013,55.935 76.994,55.935 76.727,56.202 76.727,56.637 76.994,56.905 78.062,56.905 78.159,57.002 78.159,57.197 78.062,57.295 76.994,57.295 76.727,57.562 76.727,57.997 76.994,58.265 78.062,58.265 78.159,58.362 78.159,58.557 78.062,58.655 76.994,58.655 76.727,58.922 76.727,59.357 76.994,59.625 78.062,59.625 78.159,59.722 78.159,59.917 78.062,60.015 76.994,60.015 76.727,60.282 76.727,60.717 76.994,60.985 78.062,60.985 78.159,61.082 78.159,61.277 78.062,61.375 76.994,61.375 76.727,61.642 76.727,62.077 76.994,62.345 78.062,62.345 78.159,62.442 78.159,62.637 78.062,62.735 76.994,62.735 76.727,63.002 76.727,63.437 76.994,63.705 78.013,63.705 78.11,63.802 78.11,64.612 78.11,64.81 78.69,65.39 79.48,65.39 79.855,65.765 79.855,73.405 J3.12@79.8,73.46
Ethernet_Pair1_N: J3.6 J10.5 | length 67.9
  TOP w0.09: J10.5@76.955,25.24 77.665,25.24 77.825,25.4 77.825,25.935 79.31,27.42 79.31,30.12 85.61,36.42 85.61,44.88 79.46,51.03 79.46,57.684 79.46,58.195 79.727,58.463 81.021,58.463 81.118,58.56 81.118,58.755 81.021,58.853 79.661,58.853 79.394,59.12 79.394,59.555 79.661,59.823 81.021,59.823 81.118,59.92 81.118,60.115 81.021,60.213 79.661,60.213 79.394,60.48 79.394,60.915 79.661,61.183 81.021,61.183 81.118,61.28 81.118,61.475 81.021,61.573 79.661,61.573 79.394,61.84 79.394,62.275 79.661,62.543 81.021,62.543 81.118,62.64 81.118,62.835 81.021,62.933 79.727,62.933 79.46,63.2 79.46,63.45 79.46,63.87 81.6,66.01 81.6,71.49 81.055,72.035 81.055,73.405 J3.6@81,73.46
Ethernet_Pair1_P: J3.4 J10.4 | length 67.9
  TOP w0.09: J10.4@78.985,25.24 78.275,25.24 78.115,25.4 78.115,25.815 79.6,27.3 79.6,30 85.9,36.3 85.9,45 79.75,51.15 79.75,57.684 79.75,58.075 79.847,58.173 81.141,58.173 81.408,58.44 81.408,58.875 81.141,59.143 79.781,59.143 79.684,59.24 79.684,59.435 79.781,59.533 81.141,59.533 81.408,59.8 81.408,60.235 81.141,60.503 79.781,60.503 79.684,60.6 79.684,60.795 79.781,60.893 81.141,60.893 81.408,61.16 81.408,61.595 81.141,61.863 79.781,61.863 79.684,61.96 79.684,62.155 79.781,62.253 81.141,62.253 81.408,62.52 81.408,62.955 81.141,63.223 79.847,63.223 79.75,63.32 79.75,63.45 79.75,63.75 81.89,65.89 81.89,71.61 81.345,72.155 81.345,73.405 J3.4@81.4,73.46
Ethernet_Pair2_N: J3.9 J10.2 | length 67.7
  TOP w0.09: J3.9@80.2,76.54 80.145,76.595 80.145,77.195 80.9,77.95 83.05,77.95 84.51,76.49 84.51,50.08 87.81,46.78 87.81,25.92 87.645,25.755 87.337,25.447 87.199,25.447 86.671,25.976 86.533,25.976 86.395,25.838 86.395,25.701 86.924,25.172 86.924,25.034 86.595,24.705 85.89,24 82.7,24 82.175,24.525 82.175,25.1 82.315,25.24 J10.2@83.045,25.24
Ethernet_Pair2_P: J3.11 J10.3 | length 68
  TOP w0.09: J3.11@79.8,76.54 79.855,76.595 79.855,77.315 80.78,78.24 83.17,78.24 84.8,76.61 84.8,50.2 88.1,46.9 88.1,25.8 86.01,23.71 82.58,23.71 81.885,24.405 81.885,25.1 81.745,25.24 J10.3@81.015,25.24
Ethernet_Pair3_N: J3.5 J10.9 | length 67.6
  TOP w0.09: J3.5@81,76.54 81.055,76.595 81.055,77.12 81.375,77.44 82.36,77.44 83.365,76.435 83.365,57.754 83.365,57.255 83.098,56.987 82.392,56.987 82.295,56.89 82.295,56.695 82.392,56.597 83.135,56.597 83.402,56.33 83.402,55.895 83.135,55.627 82.392,55.627 82.295,55.53 82.295,55.335 82.392,55.237 83.135,55.237 83.402,54.97 83.402,54.535 83.135,54.267 82.392,54.267 82.295,54.17 82.295,53.975 82.392,53.877 83.135,53.877 83.402,53.61 83.402,53.175 83.135,52.907 82.392,52.907 82.295,52.81 82.295,52.615 82.392,52.517 83.098,52.517 83.365,52.25 83.365,52 83.365,49.535 87,45.9 87,35.7 80.8,29.5 80.8,27.3 81.3,26.8 82.59,26.8 82.905,27.115 82.905,27.65 82.775,27.78 J10.9@82.035,27.78
Ethernet_Pair3_P: J3.3 J10.8 | length 67.6
  TOP w0.09: J3.3@81.4,76.54 81.345,76.595 81.345,77 81.495,77.15 82.24,77.15 83.075,76.315 83.075,57.754 83.075,57.375 82.978,57.277 82.272,57.277 82.005,57.01 82.005,56.575 82.272,56.307 83.015,56.307 83.112,56.21 83.112,56.015 83.015,55.917 82.272,55.917 82.005,55.65 82.005,55.215 82.272,54.947 83.015,54.947 83.112,54.85 83.112,54.655 83.015,54.557 82.272,54.557 82.005,54.29 82.005,53.855 82.272,53.587 83.015,53.587 83.112,53.49 83.112,53.295 83.015,53.197 82.272,53.197 82.005,52.93 82.005,52.495 82.272,52.227 82.978,52.227 83.075,52.13 83.075,52 83.075,49.415 86.71,45.78 86.71,35.82 80.51,29.62 80.51,27.18 81.18,26.51 82.71,26.51 83.195,26.995 83.195,27.65 83.325,27.78 J10.8@84.065,27.78
FGND: C8.1 C11.2 FGND.1 | length 7.3
  TOP w1: C11.2@162.2,28.47 162.465,28.735 C8.1@162.465,31 162.465,32.665 FGND.1@164.6,34.8
GLOBAL_EN: J2.10 J3.99 U2.4 | length 40.6
  TOP w0.2: U2.4@32.47,68.45 33.15,68.45 33.6,68.9 33.6,75.05 J2.10@32.92,75.73 ; J3.99@62.2,76.54 v1(62.2,77.5)
  BOT w0.2: J2.10@32.92,75.73 34.19,77 45.3,77 47.2,78.9 60.6,78.9 62,77.5 v1(62.2,77.5)
GND: C1.2 C2.2 C3.2 C4.2 C5.2 C10.2 C11.1 DC1.2 FL1.2 R1.1
  other v1: 159.5,24.6 160.3,24.6 161.4,24.6 162.1,24.6 162.9,24.6 164.1,24.6 164.9,24.6 159.5,25.3 160.3,25.3 160.6,52.6 160.6,53.4 160.6,54.8 160.6,55.6 160.6,56.8 160.6,57.6 160.6,59.2 160.6,60 160.6,61.2 160.6,62
GND_ISO: C15.2 C16.1 C90.2 C91.2 C104.2 C105.2 C108.2 C109.2 C114.2 C115.2 DC2.3 FL2.2 FL2.4 FL4.2 FL4.4 FL5.2 FL5.4 FL7.2 FL7.4 FL8.2 FL8.4 FL10.2 FL10.4 FL11.2 FL11.4 FL13.2 FL13.4 IC2.5 IC3.5 R3.1 R46.1 R51.1 U17.7 U19.7 | length 38
  TOP w0.4: v1(7.4,12.8) FL4.2@8,12.8 FL4.4@8.8,12.8 FL2.2@10,12.8 FL2.4@10.8,12.8 v1(11.6,12.8) ; v1(19.2,12.8) FL7.2@19.8,12.8 FL7.4@20.6,12.8 FL5.2@21.8,12.8 FL5.4@22.6,12.8 v1(23.4,12.8) ; v1(29.4,12.8) FL8.2@30,12.8 FL8.4@30.8,12.8 FL10.2@32,12.8 FL10.4@32.8,12.8 v1(33.6,12.8) ; v1(39.6,12.8) FL11.2@40.2,12.8 FL11.4@41,12.8 FL13.2@42.2,12.8 FL13.4@43,12.8 v1(43.8,12.8)
  TOP w0.5: v1(5.6,18.7) R3.1@5.6,19.575 ; 10.9,23.8 11.035,23.665 U17.7@11.035,22.45 11.035,21.545 v1(11.28,21.3) ; 22.9,23.8 22.835,23.735 U19.7@22.835,22.45 22.835,21.545 v1(23.08,21.3) ; v1(29.4,26) 29.495,25.905 IC2.5@29.495,24.4 ; v1(33.7,13.8) 33.825,13.925 R46.1@33.825,15.2 ; v1(39.6,26) 39.695,25.905 IC3.5@39.695,24.4 ; v1(43.9,13.8) 44.025,13.925 R51.1@44.025,15.2
  BOT w0.5: C91.2@11.09,23.6 C90.2@11.09,22.2 11.09,21.49 v1(11.28,21.3) ; C104.2@22.89,23.6 C105.2@22.89,22.2 22.89,21.49 v1(23.08,21.3) ; v1(32.28,26.2) 32.29,26.19 C108.2@32.29,25.4 C109.2@32.29,24.2 ; C115.2@42.29,24.2 C114.2@42.29,25.4 42.29,26.01 v1(42.48,26.2)
  other v1: 10.4,1.2 18,1.2 26,1.2 28,1.2 31.2,1.2 36,1.2 42.4,1.2 46.4,1.2 8.4,2 47.2,2.8 28,4 8.4,5.6 28,8 5.6,8.4 1.2,10 13.6,12.8 28,12.8 13.6,16 1.2,17.6 36,19.6 45.2,19.6 25.2,20 13.6,20.4 36,22.8 45.2,22.8 1.2,24 13.6,24 16,24 19.2,24 25.2,24 27.6,25.6 29.2,26.8 36,26.8 37.2,26.8 50.4,26.8 54.4,29.1 55.1,29.1 54.4,29.8 55.1,29.8 45.2,30 50.4,30 45.2,32.4 47.9,33 48.6,33 47.9,33.7 48.6,33.7
GPIO0: J3.36 J4.1 | length 34.1
  TOP w0.2: J3.36@75,73.46 75,71 v1(75.2,70.8) ; J4.1@88.08,86.27 89.3,85.05 89.3,72.9 89.9,72.3 v1(89.9,71.2)
  BOT w0.2: v1(75.2,70.8) 75.6,71.2 87.8,71.2 88.4,70.6 89.6,70.6 89.9,70.9 v1(89.9,71.2)
GPIO1: J3.35 J4.3 | length 20.6
  TOP w0.2: J3.35@75,76.54 75,85.1 77.4,87.5 84.31,87.5 J4.3@85.54,86.27
GPIO2: J3.58 J4.5 | length 37.9
  TOP w0.2: v1(70,71.4) 70.6,72 J3.58@70.6,73.46 ; J4.5@83,86.27 84.5,84.77 84.5,83.2 88.5,79.2 88.5,72.2 v1(88.7,72)
  BOT w0.2: v1(70,71.4) 70.6,72 v1(88.7,72)
GPIO3: J3.56 J4.7 | length 39.9
  TOP w0.2: v1(70.8,71.4) 70.9,71.4 71,71.5 J3.56@71,73.46 ; J4.7@80.46,86.27 81.73,85 83.6,85 84.1,84.5 84.1,83.034 88.1,79.034 88.1,71.8 v1(88.7,71.2)
  BOT w0.2: v1(70.8,71.4) 71,71.6 88.3,71.6 v1(88.7,71.2)
GPIO6: J3.30 J4.2 | length 31.8
  TOP w0.2: J3.30@76.2,73.46 76.2,71.8 77,71 77,70 v1(76.4,69.4) ; J4.2@88.08,83.73 88.9,82.91 88.9,72.7 89.3,72.3 89.3,70.3 v1(88.7,69.7)
  BOT w0.2: v1(76.4,69.4) 88.4,69.4 v1(88.7,69.7)
GPIO7: J3.37 J4.4 | length 26.1
  TOP w0.2: J3.37@74.6,76.54 74.6,85.3 77.2,87.9 85.8,87.9 86.7,87 86.7,84.89 J4.4@85.54,83.73
GPIO16: J3.29 J4.6 | length 11.6
  TOP w0.2: J3.29@76.2,76.54 76.2,79.6 79.2,82.6 81.2,82.6 82.33,83.73 J4.6@83,83.73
